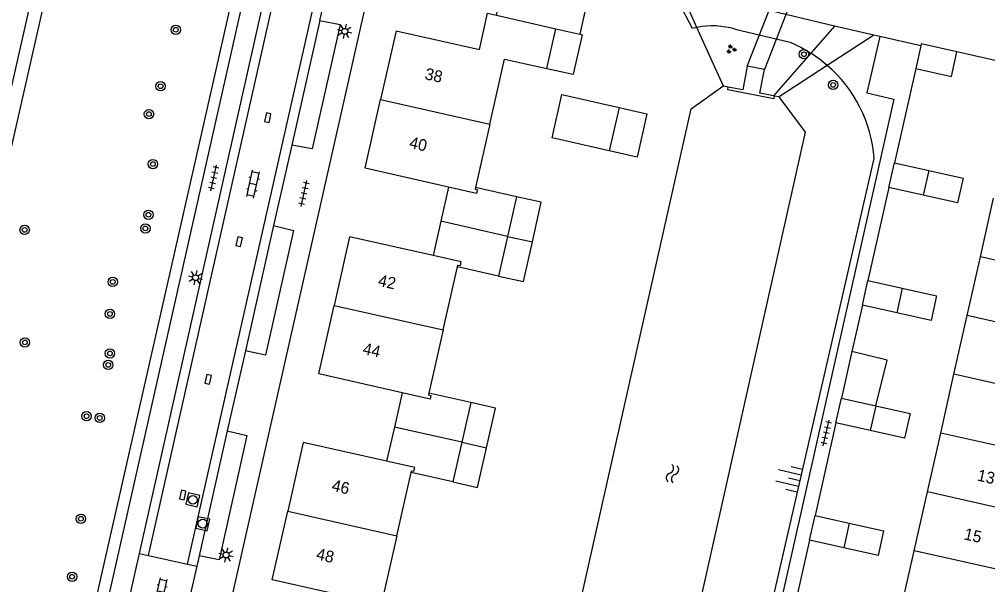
# Model space of a CAD drawing. Extents: x 128000 to 131008, y 398996 to 402500.
# Drawn here: x 128773.8 to 128856.3, y 399254.2 to 399302.4 of the extents above; entities that cross this region are included whole.
import ezdxf

# ---------------------------------------------------------------- set-up
doc = ezdxf.new("R2010")
doc.units = 0
for name, color, linetype in [('gg-afsc-erfafscheiding', 7, 'Continuous'), ('gg-afsc-hekwerk', 7, 'Continuous'), ('gg-anno-huisnummerreeks BGT', 7, 'Continuous'), ('gg-bbg-bijgebouw', 7, 'Continuous'), ('gg-bbg-gedigitaliseerde bijgebouw', 7, 'Continuous'), ('gg-bbg-hoofdgebouw', 7, 'Continuous'), ('gg-bbg-luifel en loopbrug', 7, 'Continuous'), ('gg-bbg-tussenscheiding', 7, 'Continuous'), ('gg-knt-BGT kruinlijn', 7, 'Continuous'), ('gg-knt-verharding', 7, 'Continuous'), ('gg-knt-verharding nz', 7, 'Continuous'), ('gg-kntw-beschoeiing', 7, 'Continuous'), ('gg-kwrk-duiker nz vlak', 7, 'Continuous'), ('gg-kwrk-uitstroombak niveau min 01', 7, 'Continuous'), ('gt-grn-groengrens', 7, 'Continuous'), ('gt-symb-boom', 7, 'Continuous'), ('gt-symb-groenvak', 7, 'Continuous'), ('gt-symb-klinker verharding', 7, 'Continuous'), ('gt-symb-kolk', 7, 'Continuous'), ('gt-symb-lichtmast', 7, 'Continuous'), ('gt-symb-rioolschacht', 7, 'Continuous'), ('gt-symb-talud symbool', 7, 'Continuous'), ('gt-symb-tegel verharding', 7, 'Continuous'), ('gt-symb-watersymbool', 7, 'Continuous')]:
    doc.layers.add(name, color=color, linetype=linetype)

# ---------------------------------------------------------------- blocks, each defined once
blk = doc.blocks.new('gt0-BOOM')
at = {"layer": 'gt-symb-boom'}
for radius in [0.4, 0.2]:
    blk.add_circle((0, 0), radius, dxfattribs=at)
blk = doc.blocks.new('gt0-TALUD_1')
at = {"layer": 'gt-symb-talud symbool'}
for p, q in [((-1, -1), (-1, 0)), ((-0.5, -2), (-0.5, 0)), ((0.5, -2), (0.5, 0)), ((1, -1), (1, 0)), ((0, -1), (0, 0))]:
    blk.add_line(p, q, dxfattribs=at)
blk = doc.blocks.new('gt0-WA')
at = {"layer": 'gt-symb-watersymbool'}
for centre, start, end in [((-0.323, 0.022), 28.07249, 151.92751), ((0.427, 0.422), 208.07248, 331.92751), ((-0.323, -0.428), 28.07249, 151.92751), ((0.427, -0.028), 208.07248, 331.92751)]:
    blk.add_arc(centre, 0.425, start, end, dxfattribs=at)
blk = doc.blocks.new('gt0-TEG1')
at = {"layer": 'gt-symb-tegel verharding'}
for p, q in [((-1.125, 0), (1.125, 0)), ((-0.9, -0.25), (-0.9, 0.25)), ((-0.45, -0.25), (-0.45, 0.25)), ((0, -0.25), (0, 0.25)), ((0.45, -0.25), (0.45, 0.25)), ((0.9, -0.25), (0.9, 0.25))]:
    blk.add_line(p, q, dxfattribs=at)
blk = doc.blocks.new('gt0-GRVAK')
at = {"layer": 'gt-symb-groenvak'}
for p, q in [((-0.11, 0.189), (-0.228, 0.24)), ((-0.182, 0.153), (0.088, 0.153)), ((-0.091, 0.211), (-0.156, 0.322)), ((-0.047, 0.214), (-0.047, 0.393)), ((-0.004, 0.211), (0.061, 0.322)), ((0.015, 0.189), (0.133, 0.24)), ((0.262, -0.052), (0.197, 0.059)), ((0.305, -0.049), (0.305, 0.13)), ((0.349, -0.052), (0.414, 0.059)), ((-0.245, -0.228), (-0.363, -0.177)), ((-0.318, -0.264), (-0.047, -0.264)), ((-0.226, -0.206), (-0.291, -0.095)), ((-0.183, -0.203), (-0.183, -0.024)), ((-0.139, -0.206), (-0.074, -0.095)), ((-0.12, -0.228), (-0.002, -0.177)), ((0.243, -0.074), (0.125, -0.023)), ((0.17, -0.11), (0.441, -0.11)), ((0.368, -0.074), (0.486, -0.023))]:
    blk.add_line(p, q, dxfattribs=at)
blk = doc.blocks.new('gt0-KL1')
at = {"layer": 'gt-symb-klinker verharding'}
for p, q in [((-1.15, 0.3), (1.15, 0.3)), ((-1, -0.3), (-1, 0.3)), ((-0.5, 0.3), (-0.5, 0.45)), ((0, -0.3), (0, 0.3)), ((0.5, 0.3), (0.5, 0.45)), ((1, -0.3), (1, 0.3)), ((-1.15, -0.3), (1.15, -0.3)), ((-0.5, -0.45), (-0.5, -0.3)), ((0.5, -0.45), (0.5, -0.3))]:
    blk.add_line(p, q, dxfattribs=at)
blk = doc.blocks.new('gt0-LMAST')
at = {"layer": 'gt-symb-lichtmast'}
for p, q in [((-0.182, 0.173), (-0.447, 0.438)), ((-0.005, 0.246), (-0.005, 0.621)), ((0.172, 0.173), (0.437, 0.438)), ((-0.255, -0.004), (-0.63, -0.004)), ((-0.182, -0.181), (-0.447, -0.446)), ((-0.005, -0.254), (-0.005, -0.629)), ((0.437, -0.446), (0.172, -0.181)), ((0.245, -0.004), (0.62, -0.004))]:
    blk.add_line(p, q, dxfattribs=at)
blk.add_circle((-0.005, -0.004), 0.25, dxfattribs=at)
blk = doc.blocks.new('gt0-RS')
at = {"layer": 'gt-symb-rioolschacht'}
blk.add_lwpolyline([(-0.5, -0.5), (0.5, -0.5), (0.5, 0.5), (-0.5, 0.5)], close=True, dxfattribs=at)
blk.add_circle((0, 0), 0.375, dxfattribs=at)
blk = doc.blocks.new('gt0-KOLK')
at = {"layer": 'gt-symb-kolk'}
blk.add_lwpolyline([(0, 0), (0.375, 0), (0.375, 0.4), (-0.375, 0.4), (-0.375, 0), (0, 0)], dxfattribs=at)

msp = doc.modelspace()

# ---------------------------------------------------------------- linework, layer by layer
at = {"layer": 'gg-afsc-erfafscheiding'}
for p, q in [((128831.554, 399301.755), (128830.067, 399305.053)), ((128833.816, 399296.739), (128831.554, 399301.755)), ((128850.21, 399298.24), (128848.396, 399290.19)), ((128847.926, 399288.09), (128846.138, 399280.154)), ((128845.668, 399278.054), (128844.777, 399274.101)), ((128843.411, 399268.022), (128841.624, 399260.089)), ((128841.154, 399257.989), (128839.367, 399250.056))]:
    msp.add_line(p, q, dxfattribs=at)
at = {"layer": 'gg-afsc-hekwerk'}
for p, q in [((128843.297, 399301.849), (128841.282, 399299.553)), ((128846.627, 399301.09), (128843.297, 399301.849)), ((128847.145, 399300.972), (128846.627, 399301.09)), ((128850.643, 399300.174), (128847.145, 399300.972)), ((128841.282, 399299.553), (128838.087, 399295.911))]:
    msp.add_line(p, q, dxfattribs=at)
at = {"layer": 'gg-bbg-bijgebouw'}
for p, q in [((128850.643, 399300.174), (128850.21, 399298.24)), ((128818.747, 399298.258), (128821.013, 399297.761))]:
    msp.add_line(p, q, dxfattribs=at)
for points in [[(128819.519, 399301.634), (128819.534, 399301.63), (128821.564, 399301.174)], [(128821.564, 399301.174), (128821.771, 399301.127), (128821.013, 399297.761)], [(128853.72, 399299.66), (128850.68, 399300.34), (128850.643, 399300.174)], [(128850.21, 399298.24), (128853.25, 399297.56), (128853.72, 399299.66)]]:
    msp.add_lwpolyline(points, dxfattribs=at)
at = {"layer": 'gg-bbg-gedigitaliseerde bijgebouw'}
for p, q in [((128847.926, 399288.09), (128848.396, 399290.19)), ((128848.396, 399290.19), (128851.322, 399289.535)), ((128850.852, 399287.435), (128847.926, 399288.09)), ((128816.179, 399287.307), (128815.413, 399283.922)), ((128815.413, 399283.922), (128814.648, 399280.538)), ((128845.668, 399278.054), (128846.138, 399280.154)), ((128846.138, 399280.154), (128849.064, 399279.499)), ((128848.594, 399277.399), (128845.668, 399278.054)), ((128843.411, 399268.022), (128843.881, 399270.122)), ((128843.881, 399270.122), (128846.807, 399269.467)), ((128812.273, 399269.735), (128811.507, 399266.35)), ((128846.337, 399267.367), (128843.411, 399268.022)), ((128811.507, 399266.35), (128810.742, 399262.966)), ((128841.154, 399257.989), (128841.624, 399260.089)), ((128841.624, 399260.089), (128844.55, 399259.434)), ((128844.08, 399257.334), (128841.154, 399257.989))]:
    msp.add_line(p, q, dxfattribs=at)
for points in [[(128851.322, 399289.535), (128854.247, 399288.881), (128853.777, 399286.781), (128850.852, 399287.435)], [(128817.52, 399283.446), (128818.285, 399286.83), (128816.179, 399287.307)], [(128814.648, 399280.538), (128816.754, 399280.061), (128817.52, 399283.446)], [(128849.064, 399279.499), (128851.989, 399278.845), (128851.519, 399276.745), (128848.594, 399277.399)], [(128813.614, 399265.874), (128814.379, 399269.258), (128812.273, 399269.735)], [(128846.807, 399269.467), (128849.732, 399268.813), (128849.262, 399266.713), (128846.337, 399267.367)], [(128810.742, 399262.966), (128812.848, 399262.489), (128813.614, 399265.874)], [(128844.55, 399259.434), (128847.475, 399258.78), (128847.005, 399256.68), (128844.08, 399257.334)]]:
    msp.add_lwpolyline(points, dxfattribs=at)
at = {"layer": 'gg-bbg-hoofdgebouw'}
for p, q in [((128814.451, 399302.791), (128819.519, 399301.634)), ((128805.91, 399301.46), (128804.585, 399295.595)), ((128813.89, 399293.493), (128812.676, 399288.099)), ((128855.725, 399282.179), (128856.854, 399287.195)), ((128854.597, 399277.163), (128855.725, 399282.179)), ((128809.925, 399275.938), (128811.143, 399281.33)), ((128853.468, 399272.148), (128854.597, 399277.163)), ((128809.925, 399275.938), (128808.706, 399270.541)), ((128852.34, 399267.132), (128853.468, 399272.148)), ((128851.211, 399262.116), (128852.34, 399267.132)), ((128805.958, 399258.37), (128807.178, 399263.772)), ((128850.082, 399257.1), (128851.211, 399262.116)), ((128805.958, 399258.37), (128804.741, 399252.981)), ((128848.953, 399252.084), (128850.082, 399257.1))]:
    msp.add_line(p, q, dxfattribs=at)
for points in [[(128805.91, 399301.46), (128813.011, 399299.882), (128813.699, 399302.963), (128814.451, 399302.791)], [(128813.89, 399293.493), (128815.14, 399299.05), (128818.747, 399298.258)], [(128810.375, 399288.129), (128803.26, 399289.73), (128804.585, 399295.595)], [(128812.676, 399288.099), (128812.64, 399287.94), (128812.84, 399287.9), (128812.77, 399287.59), (128810.375, 399288.129)], [(128809.054, 399282.285), (128801.94, 399283.89), (128800.62, 399278.035)], [(128811.143, 399281.33), (128811.176, 399281.477), (128811.38, 399281.431), (128811.451, 399281.744), (128809.054, 399282.285)], [(128806.413, 399270.57), (128799.3, 399272.18), (128800.62, 399278.035)], [(128808.706, 399270.541), (128808.671, 399270.387), (128808.875, 399270.341), (128808.805, 399270.029), (128806.413, 399270.57)], [(128805.092, 399264.725), (128797.98, 399266.33), (128796.655, 399260.475)], [(128807.178, 399263.772), (128807.211, 399263.918), (128807.416, 399263.872), (128807.487, 399264.185), (128805.092, 399264.725)], [(128802.41, 399253.019), (128795.33, 399254.62), (128796.655, 399260.475)]]:
    msp.add_lwpolyline(points, dxfattribs=at)
at = {"layer": 'gg-bbg-luifel en loopbrug'}
for p, q in [((128824.916, 399294.927), (128824.078, 399291.221)), ((128810.375, 399288.129), (128809.715, 399285.207)), ((128816.179, 399287.307), (128812.676, 399288.099)), ((128809.715, 399285.207), (128809.054, 399282.285)), ((128815.413, 399283.922), (128809.715, 399285.207)), ((128814.648, 399280.538), (128811.143, 399281.33)), ((128844.777, 399274.101), (128843.881, 399270.122)), ((128806.413, 399270.57), (128805.752, 399267.648)), ((128812.273, 399269.735), (128808.706, 399270.541)), ((128805.752, 399267.648), (128805.092, 399264.725)), ((128811.507, 399266.35), (128805.752, 399267.648)), ((128810.742, 399262.966), (128807.178, 399263.772))]:
    msp.add_line(p, q, dxfattribs=at)
for points in [[(128814.451, 399302.791), (128814.8, 399304.335), (128817.653, 399303.69), (128818.314, 399306.616), (128820.625, 399306.094), (128820.768, 399306.725), (128822.719, 399306.284), (128821.564, 399301.174)], [(128824.078, 399291.221), (128819.201, 399292.323), (128820.039, 399296.03), (128824.916, 399294.927)], [(128824.916, 399294.927), (128827.285, 399294.392), (128826.447, 399290.685), (128824.078, 399291.221)], [(128846.807, 399269.467), (128847.782, 399273.346), (128844.777, 399274.101)]]:
    msp.add_lwpolyline(points, dxfattribs=at)
at = {"layer": 'gg-bbg-tussenscheiding'}
for p, q in [((128818.747, 399298.258), (128819.519, 399301.634)), ((128804.585, 399295.595), (128813.89, 399293.493)), ((128851.322, 399289.535), (128850.852, 399287.435)), ((128815.413, 399283.922), (128817.52, 399283.446)), ((128864.154, 399280.282), (128855.725, 399282.179)), ((128849.064, 399279.499), (128848.594, 399277.399)), ((128800.62, 399278.035), (128809.925, 399275.938)), ((128863.026, 399275.266), (128854.597, 399277.163)), ((128861.897, 399270.251), (128853.468, 399272.148)), ((128846.807, 399269.467), (128846.337, 399267.367)), ((128860.769, 399265.235), (128852.34, 399267.132)), ((128811.507, 399266.35), (128813.614, 399265.874)), ((128859.64, 399260.219), (128851.211, 399262.116)), ((128796.655, 399260.475), (128805.958, 399258.37)), ((128844.55, 399259.434), (128844.08, 399257.334)), ((128858.512, 399255.203), (128850.082, 399257.1))]:
    msp.add_line(p, q, dxfattribs=at)
at = {"layer": 'gg-knt-BGT kruinlijn'}
for p, q in [((128831.554, 399301.755), (128831.179, 399301.671)), ((128831.568, 399224.859), (128846.68, 399290.58))]:
    msp.add_line(p, q, dxfattribs=at)
for points in [[(128834.81, 399301.6), (128839.492, 399300.489), (128840.407, 399300.059), (128841.282, 399299.553)], [(128842.67, 399298.517), (128841.999, 399299.057), (128841.282, 399299.553)]]:
    msp.add_lwpolyline(points, dxfattribs=at)
for centre, radius, start, end in [((128832.866, 399295.031), 6.851, 73.51105, 101.038), ((128834.966, 399289.643), 11.751, 4.57167, 49.03676)]:
    msp.add_arc(centre, radius, start, end, dxfattribs=at)
at = {"layer": 'gg-knt-verharding'}
for p, q in [((128771.01, 399207.09), (128794.75, 399312.45)), ((128784.013, 399256.864), (128796.011, 399310.241)), ((128799.404, 399302.355), (128800.933, 399309.135)), ((128786.527, 399229.225), (128803.644, 399305.184)), ((128843.297, 399301.849), (128830.067, 399305.053)), ((128869.28, 399296.18), (128853.72, 399299.66)), ((128797.003, 399291.704), (128795.455, 399284.838)), ((128793.049, 399274.166), (128791.508, 399267.33)), ((128782.862, 399251.741), (128784.013, 399256.864)), ((128784.013, 399256.864), (128784.794, 399256.689)), ((128784.794, 399256.689), (128788.121, 399255.946)), ((128789.101, 399256.655), (128788.902, 399255.771)), ((128788.902, 399255.771), (128787.739, 399250.615)), ((128788.121, 399255.946), (128788.902, 399255.771))]:
    msp.add_line(p, q, dxfattribs=at)
for points in [[(128799.404, 399302.355), (128801.14, 399302.004), (128798.736, 399291.381), (128797.003, 399291.704)], [(128847.145, 399300.972), (128846.048, 399296.162), (128848.332, 399295.641), (128831.168, 399219.189), (128829.93, 399219.468), (128829.692, 399218.416)], [(128795.455, 399284.838), (128797.144, 399284.413), (128794.758, 399273.779), (128793.049, 399274.166)], [(128791.508, 399267.33), (128793.184, 399266.935), (128790.804, 399256.327), (128789.101, 399256.655)]]:
    msp.add_lwpolyline(points, dxfattribs=at)
at = {"layer": 'gg-knt-verharding nz'}
for p, q in [((128784.794, 399256.689), (128796.81, 399310.061)), ((128788.121, 399255.946), (128800.152, 399309.31)), ((128799.404, 399302.355), (128797.003, 399291.704)), ((128795.455, 399284.838), (128793.049, 399274.166)), ((128791.508, 399267.33), (128789.101, 399256.655))]:
    msp.add_line(p, q, dxfattribs=at)
at = {"layer": 'gg-kntw-beschoeiing'}
for p, q in [((128834.225, 399296.659), (128833.816, 399296.739)), ((128838.56, 399295.82), (128838.151, 399295.899))]:
    msp.add_line(p, q, dxfattribs=at)
for points in [[(128818.476, 399225.699), (128818.195, 399225.754), (128816.24, 399228.83), (128831.05, 399294.8), (128833.76, 399296.75), (128833.816, 399296.739)], [(128822.513, 399224.91), (128822.96, 399224.83), (128826.07, 399226.9), (128840.8, 399292.8), (128838.56, 399295.82)]]:
    msp.add_lwpolyline(points, dxfattribs=at)
at = {"layer": 'gg-kwrk-duiker nz vlak'}
for p, q in [((128835.85, 399298.46), (128845.66, 399323.69)), ((128847.14, 399323.41), (128837.32, 399298.17))]:
    msp.add_line(p, q, dxfattribs=at)
at = {"layer": 'gg-kwrk-uitstroombak niveau min 01'}
for p, q in [((128837.32, 399298.17), (128835.85, 399298.46)), ((128838.151, 399295.899), (128838.087, 399295.911))]:
    msp.add_line(p, q, dxfattribs=at)
for points in [[(128835.85, 399298.46), (128835.457, 399296.421), (128834.225, 399296.659)], [(128838.087, 399295.911), (128836.925, 399296.137), (128837.32, 399298.17)], [(128838.151, 399295.899), (128838.104, 399295.656), (128834.178, 399296.415), (128834.225, 399296.659)]]:
    msp.add_lwpolyline(points, dxfattribs=at)
at = {"layer": 'gt-grn-groengrens'}
for p, q in [((128757.572, 399227.825), (128777.956, 399318.179)), ((128831.179, 399301.671), (128829.307, 399305.227)), ((128846.627, 399301.09), (128842.67, 399298.517)), ((128842.67, 399298.517), (128838.56, 399295.82))]:
    msp.add_line(p, q, dxfattribs=at)
msp.add_lwpolyline([(128755.023, 399211.895), (128770.192, 399208.416), (128793.712, 399312.097), (128792.738, 399314.463), (128778.96, 399317.525), (128755.023, 399211.895)], dxfattribs=at)

# ---------------------------------------------------------------- block references
at = {"layer": 'gt-symb-boom'}
for p in [(128787.117, 399301.549), (128785.813, 399296.735), (128784.829, 399294.361), (128785.169, 399290.089), (128784.779, 399285.762), (128774.227, 399284.478), (128784.523, 399284.594), (128781.741, 399280.034), (128781.493, 399277.3), (128774.251, 399274.873), (128781.5, 399273.933), (128781.359, 399272.948), (128779.503, 399268.573), (128780.634, 399268.424), (128779.022, 399259.823), (128778.267, 399254.879)]:
    msp.add_blockref('gt0-BOOM', p, dxfattribs=at)
for p, rotation in [((128840.684, 399299.46), 167.22875743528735), ((128843.173, 399296.85), 167.22875743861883)]:
    msp.add_blockref('gt0-BOOM', p, dxfattribs=dict(at, rotation=rotation))
at = {"layer": 'gt-symb-groenvak'}
msp.add_blockref('gt0-GRVAK', (128834.466, 399299.888), dxfattribs=at)
at = {"layer": 'gt-symb-klinker verharding'}
for p, rotation in [((128793.711, 399288.377), 77.35314649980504), ((128785.841, 399253.589), 77.17287657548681)]:
    msp.add_blockref('gt0-KL1', p, dxfattribs=dict(at, rotation=rotation))
at = {"layer": 'gt-symb-kolk'}
for p, rotation in [((128795.15, 399294.006), 77.17287657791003), ((128792.72, 399283.423), 77.17287657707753), ((128790.073, 399271.67), 77.17287657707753), ((128787.901, 399261.812), 77.17287657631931)]:
    msp.add_blockref('gt0-KOLK', p, dxfattribs=dict(at, rotation=rotation))
at = {"layer": 'gt-symb-lichtmast'}
for p, rotation in [((128801.521, 399301.425), 77.17287657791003), ((128788.791, 399280.4), 77.17287657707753), ((128791.405, 399256.735), 77.17287657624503)]:
    msp.add_blockref('gt0-LMAST', p, dxfattribs=dict(at, rotation=rotation))
at = {"layer": 'gt-symb-rioolschacht', "rotation": -102.64685349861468}
for p in [(128788.568, 399261.438), (128789.411, 399259.403)]:
    msp.add_blockref('gt0-RS', p, dxfattribs=at)
at = {"layer": 'gt-symb-talud symbool', "xscale": 1.0004004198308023, "yscale": 1.0004004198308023, "rotation": -102.93881062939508}
msp.add_blockref('gt0-TALUD_1', (128840.337, 399263.088), dxfattribs=at)
at = {"layer": 'gt-symb-tegel verharding'}
for p, rotation in [((128790.347, 399288.909), 77.35314650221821), ((128798.048, 399287.58), 77.35314650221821), ((128842.588, 399267.153), 76.88085536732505)]:
    msp.add_blockref('gt0-TEG1', p, dxfattribs=dict(at, rotation=rotation))
at = {"layer": 'gt-symb-watersymbool', "rotation": 76.82507339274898}
msp.add_blockref('gt0-WA', (128829.454, 399263.614), dxfattribs=at)

# ---------------------------------------------------------------- texts
at = {"layer": 'gg-anno-huisnummerreeks BGT'}
for s, rotation, p in [('38', 347.3, (128808.285, 399297.346)), ('40', 347.3, (128806.96, 399291.481)), ('42', 347.3, (128804.303, 399279.715)), ('44', 347.3, (128802.99, 399273.893)), ('13', 347.3, (128855.39, 399263.093)), ('46', 347.2, (128800.354, 399262.221)), ('15', 347.4, (128854.262, 399258.074)), ('48', 347.2, (128799.029, 399256.366))]:
    msp.add_text(s, height=1, rotation=rotation, dxfattribs=at).set_placement(p)

doc.saveas('drawing.dxf')
